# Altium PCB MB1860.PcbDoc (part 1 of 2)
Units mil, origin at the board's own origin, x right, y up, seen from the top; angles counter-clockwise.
Board outline 5005.03 x 3784.67 mil, 2 copper layers (Top Layer, Bottom Layer), stack 61.811 mil thick; 42 components, 46 nets, 183 pads, 524 vias.
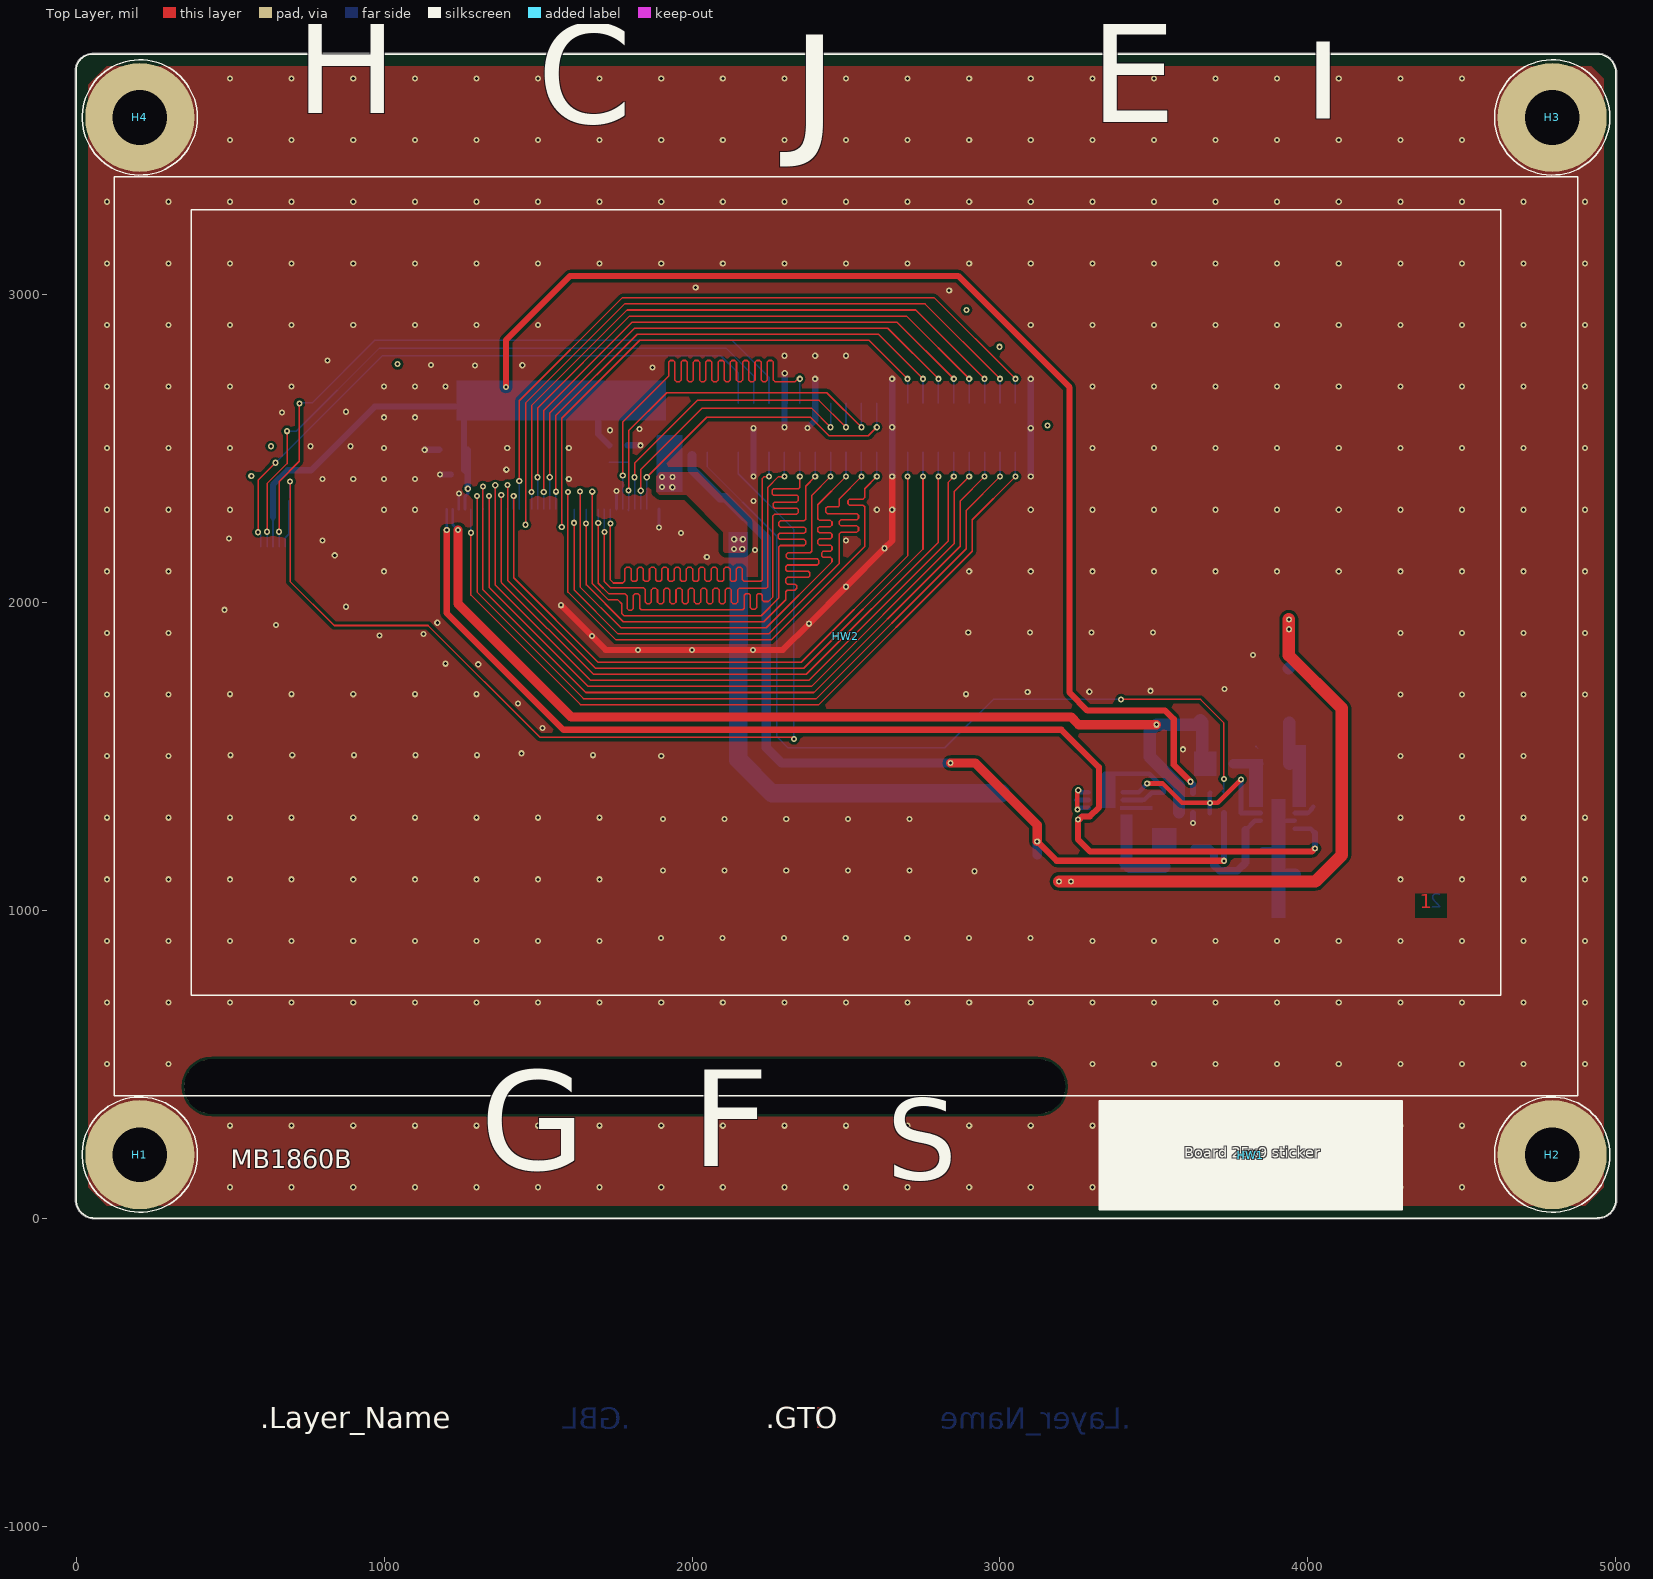
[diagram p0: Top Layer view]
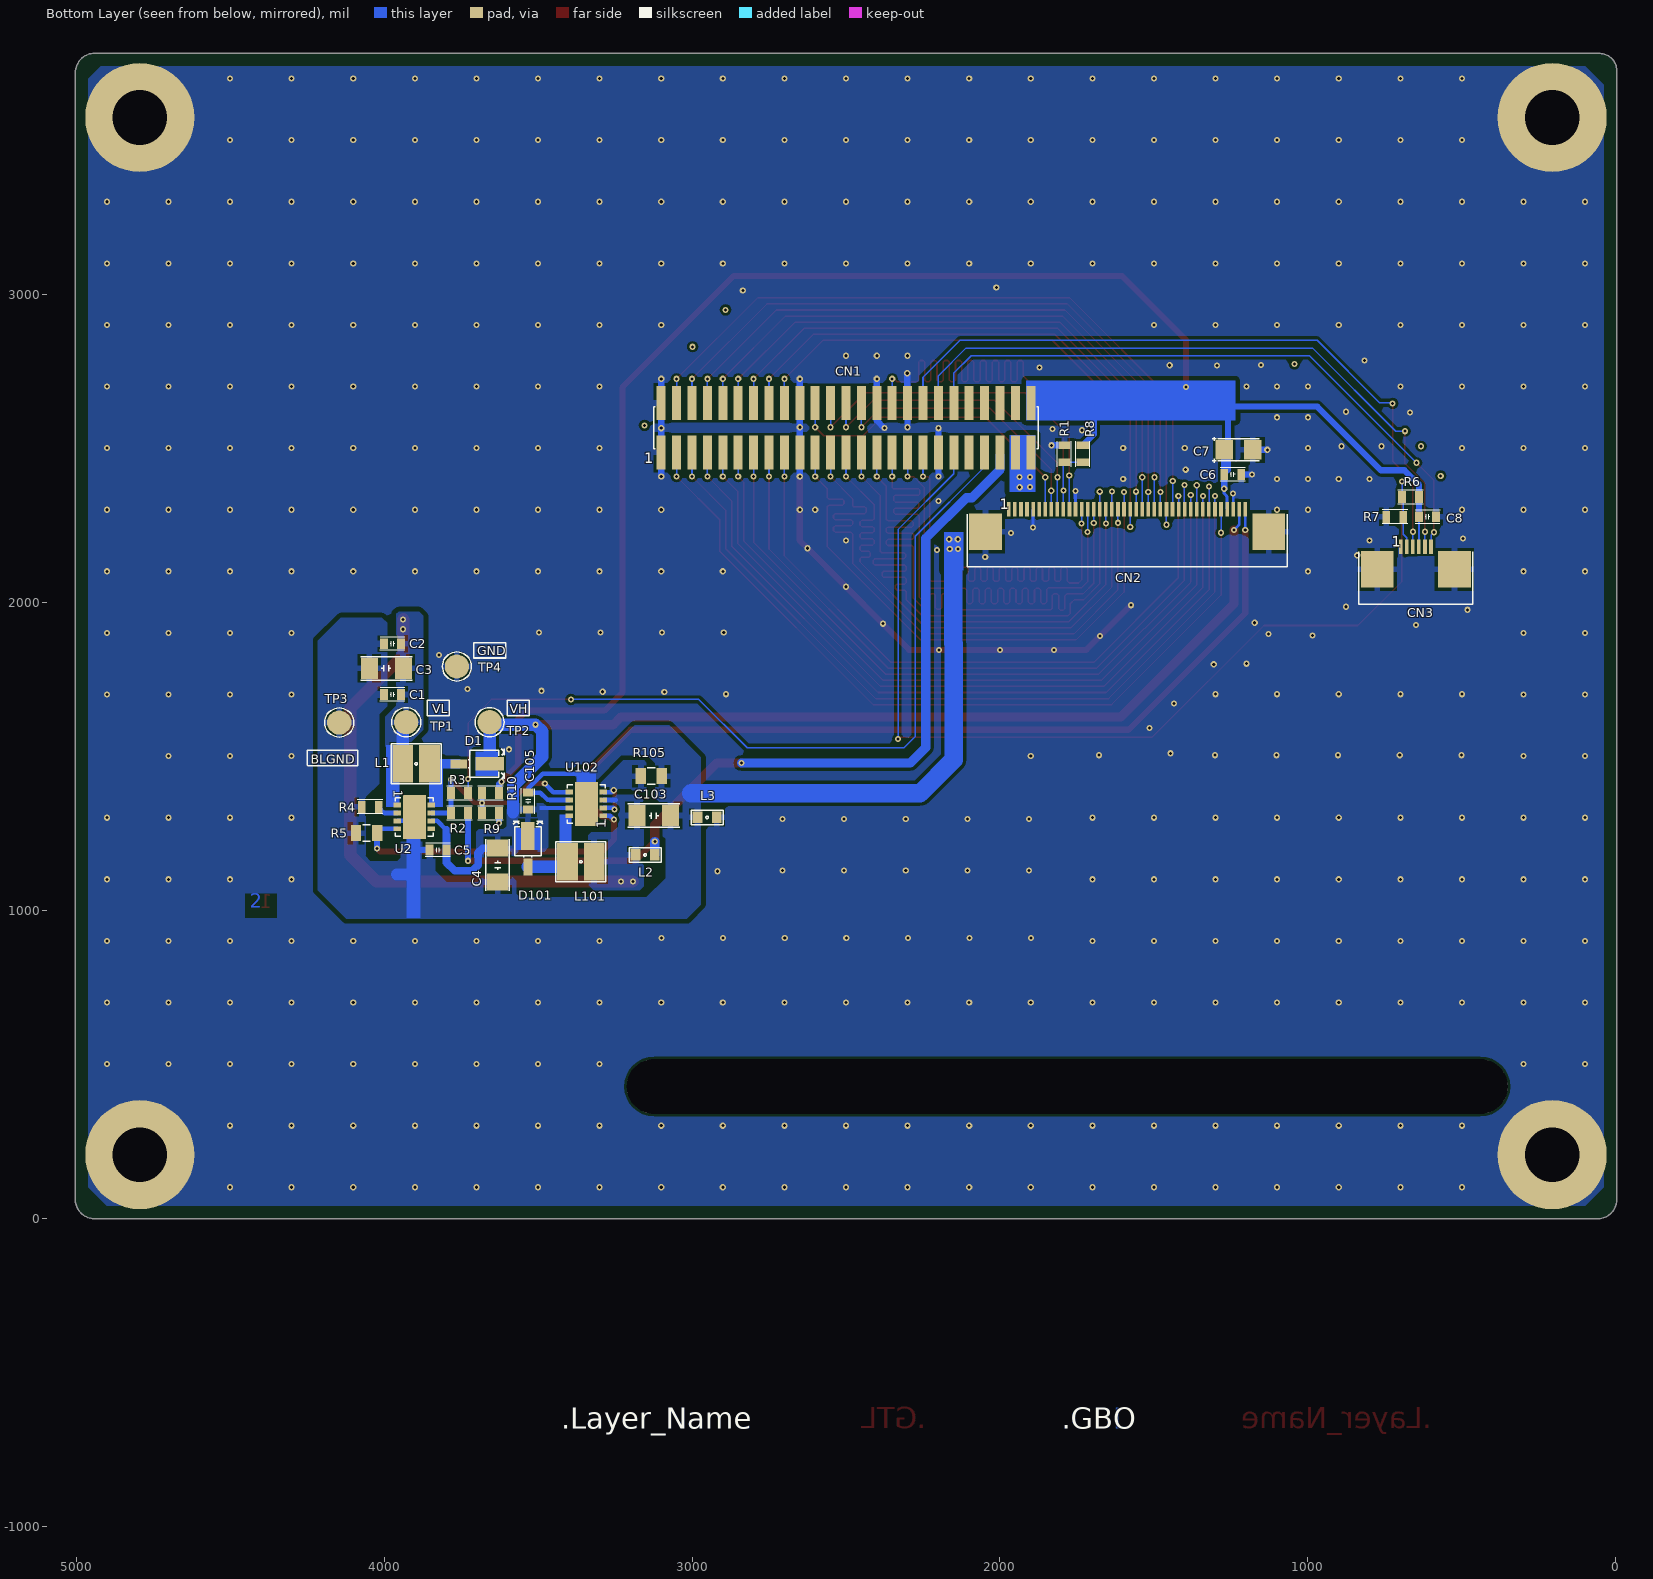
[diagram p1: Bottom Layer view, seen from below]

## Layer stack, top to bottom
Top Solder: solder mask 0.591, Solder Resist, Dk 3.5
Top Layer: signal copper 1.378
Dielectric 1: dielectric 59.055, FR-4, Dk 4.8
Bottom Layer: signal copper 1.378
Bottom Solder: solder mask 0.591, Solder Resist, Dk 3.5

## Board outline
-2.51,57 -2.51,59.51 cw(c60.38,60.26) -2.51,61.01 -2.51,3726 cw(c0,3726) -2.49,3726.34 cw(c0,3726.65) -2.51,3726.68 cw(c53.06,3726) 51.58,3781.56 cw(c53.06,3779.53) 53.06,3782.04 4939.79,3782.04 cw(c4940,3779.54) 4940.03,3782.05 cw(c4939.27,3719.16) 5002.15,3720.31 cw(c5000,3719) 5002.51,3719 5002.51,58 cw(c5000,58) 5002.43,57.34 cw(c4939.62,60.73) 4941.33,-2.14 cw(c4940,0) 4940,-2.52 62.36,-2.52 cw(c61.64,-0.1) 61.69,-2.62 cw(c60.38,60.26) -2.39,56.21 cw(c0,57)

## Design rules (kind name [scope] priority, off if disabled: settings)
Clearance Clearance_1 [HasFootprint('ICC_QFN8-EPAD_3X3_P065')] p1: gap=7.87 ignorepadtopadclearanceinfootprint=FALSE except(0: Arc-Hole Track-Hole SMDPad-Hole THPad-Hole Via-Hole Fill-Hole Poly-Hole Region-Hole Text-Hole; 5: SMDPad-SMDPad; 6: Arc-Via Track-Via Via-Via Via-Fill Via-Poly Via-Region Via-Text; 10: Arc-Arc Arc-Track Arc-Fill Arc-Poly Arc-Region Track-Track Track-Fill Track-Poly Track-Region; 15: Fill-Fill Fill-Poly Fill-Region Poly-Poly Poly-Region Region-Region)
Clearance [All] p2: gap=7.87 ignorepadtopadclearanceinfootprint=FALSE except(0: Arc-Hole Track-Hole SMDPad-Hole THPad-Hole Via-Hole Fill-Hole Poly-Hole Region-Hole Text-Hole; 6: Arc-Via Track-Via; 10: Arc-Arc Arc-Track Arc-Fill Arc-Poly Arc-Region Track-Track Track-Fill Track-Poly Track-Region; 15: Fill-Fill Fill-Poly Fill-Region Poly-Poly Poly-Region Region-Region)
ComponentClearance [All] p1: gap=7.87 collisioncheckmode=3 verticalgap=7.87 showdistances=FALSE
HoleSize [All] p1: absolutevalues=TRUE maxlimit=3937.01 minlimit=1 maxpercent=80.000 minpercent=20.000
MinimumSolderMaskSliver [All] p1: minsoldermaskwidth=0
PlaneConnect [All] p1: planeconnectstyle=Relief reliefexpansion=20 reliefentries=4 reliefconductorwidth=8.27 reliefairgap=8.27
PolygonConnect PolygonConnect_hole [HasFootprint('PTH_450_900')] p1: connectstyle=Direct reliefconductorwidth=10 reliefentries=4 polygonreliefangle="90 Angle" airgapwidth=10
PolygonConnect PolygonConnect_via [IsVia] p2: connectstyle=Direct reliefconductorwidth=10 reliefentries=4 polygonreliefangle="90 Angle" airgapwidth=10
PolygonConnect [All] p3: connectstyle=Relief reliefconductorwidth=20 reliefentries=4 polygonreliefangle="90 Angle" airgapwidth=10
RoutingVias [All] p1: holewidth=11.81 width=31.5 viastyle="Through Hole" minholewidth=11.81 minwidth=31.5 maxholewidth=11.81 maxwidth=31.5
SilkToSilkClearance [All] p1: silktosilkclearance=0
SilkToSolderMaskClearance [IsPad] p1: minsilkscreentomaskgap=0 clearancetoexposedcopper=TRUE
SolderMaskExpansion [All] p1: expansion=4
Width [All] p1: maxlimit=200 minlimit=5 preferedwidth=5
24 further rules are at their usual default settings.

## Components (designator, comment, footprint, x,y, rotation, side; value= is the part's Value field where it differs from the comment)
C1 "Capacitor" C0603 3972.39,1700 r180 bottom value=100nF
C2 "Capacitor" C0603 3972.39,1865 r180 bottom value=10nF
C3 "Capacitor" C1206_H1P25 3992.5,1785 r180 bottom value=4.7uF
C4 "Capacitor" C1206_H1P25 3631,1146 r90 bottom value=4.7uF
C5 "Capacitor" C0603 3824.94,1195 r180 bottom value=10nF
C6 "Capacitor" C0603 1244.44,2414.54 r0 bottom value=100nF
C7 "Cap_POL_TANA" CPOL_TAJ-A_1206_H180 1225.74,2494.54 r180 bottom value=4.7uF
C8 "Capacitor" C0603 612,2276.86 r0 bottom value=100nF
C103 "Capacitor" C1206_H1P25 3124.24,1307 r0 bottom value=4.7uF
C105 "Capacitor" C0603 3532,1353.87 r270 bottom value=100nF
CN1 "Header 25x2 LCD MODULE" CON_SAMTEC_FTSH-125-01-F-DV-K 2500,2566.22 r180 bottom locked value="Header 25x2"
CN2 "68714014022" CON_WE_68714014022 1587.4,2265.08 r180 bottom value=Socket_FFC/FPC_68714014022
CN3 "68710614022" CON_WE_68710614022 649.61,2143.05 r180 bottom value=Socket_FFC/FPC_68710614022
D1 "STPS1L40M" DIO_DO216-AA 3697.74,1475 r0 bottom
D101 "STPS1L40M" DIO_DO216-AA 3533,1199.87 r270 bottom
H1 "POSITION HOLE" PTH_450_900 207.09,205.91 r0 top locked
H2 "POSITION HOLE" PTH_450_900 4792.91,205.91 r0 top locked
H3 "POSITION HOLE" PTH_450_900 4792.91,3573.62 r0 top locked
H4 "POSITION HOLE" PTH_450_900 207.09,3573.62 r0 top locked
HW1 "STICKER_BOARD" STICKER_BOARD_25X9 3814,204 r0 top value="Sticker board"
HW2 "LCD_MODULE" LCD_DRAWING_ROCKTEK_RK050HR18-CTG 2499.99,1889.75 r0 top locked value=RK050HR18-CTG
L1 "Inductor" L1210_LQH 3895.69,1475 r180 bottom value=4.7uH
L2 "BEAD" L0603 3152.24,1179 r0 bottom value="600R @ 100MHz"
L3 "BEAD" L0603 2951,1301 r0 bottom value="600R @ 100MHz"
L101 "Inductor" L1210_LQH 3361,1157 r0 bottom value=4.7uH
R1 "Resistor" R0603 1790.72,2481.54 r270 bottom value=4K7
R2 "Resistor" R0603 3754.83,1315 r0 bottom value=4K7
R3 "Resistor" R0603 3754.83,1380 r0 bottom value=0R
R4 "Resistor" R0603 4044.94,1335 r180 bottom value=100K
R5 "Resistor" R0805_H0P5 4056.83,1250 r180 bottom value=6R2
R6 "Resistor" R0603 667,2340.86 r180 bottom value=220K
R7 "Resistor" R0603 718,2276.86 r180 bottom value=220K
R8 "Resistor" R0603 1731.43,2481.54 r270 bottom value=4K7
R9 "Resistor" R0603 3654,1315 r180 bottom value=4K7
R10 "Resistor" R0603 3654,1380 r0 bottom value=4K7
R105 "Resistor" R0805_H0P5 3132.24,1435 r0 bottom value=6R2
TP1 "Test Point" TP_SMD_2MM 3928,1610 r90 bottom
TP2 "Test Point" TP_SMD_2MM 3657.39,1610 r180 bottom
TP3 "Test Point" TP_SMD_2MM 4145.39,1609 r270 bottom
TP4 "Test Point" TP_SMD_2MM 3763.39,1791 r270 bottom
U2 "STLD40DPUR" ICC_QFN8-EPAD_3X3_P065 3901.6,1302.36 r270 bottom
U102 "TPS61042DRB" ICC_QFN8-EPAD_3X3_P065 3343.24,1344.56 r90 bottom

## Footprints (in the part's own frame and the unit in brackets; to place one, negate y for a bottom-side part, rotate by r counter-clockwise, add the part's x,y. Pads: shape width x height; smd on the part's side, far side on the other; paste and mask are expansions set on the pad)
C0603 [mm]
  rect 0.64x0.89 smd mask+0.05: 1(-0.7,0) 2(0.7,0)
  silkscreen extent -1.05,-0.55 1.02,0.55, body extent -0.9,-0.5 0.9,0.5, height 1.4
C1206_H1P25 [mm]
  rect 1.4x1.78 smd mask+0.05: 1(-1.4,0) 2(1.4,0)
  silkscreen extent -2.12,-0.97 2.15,0.97, body extent -1.7,-0.9 1.7,0.9, height 1.45
CON_SAMTEC_FTSH-125-01-F-DV-K [mm]
  rect 0.74x2.79 smd mask+0.05: 1(-15.24,-2.035) 2(-15.24,2.035) 3(-13.97,-2.035) 4(-13.97,2.035) 5(-12.7,-2.035) 6(-12.7,2.035) 7(-11.43,-2.035) 8(-11.43,2.035) 9(-10.16,-2.035) 10(-10.16,2.035) 11(-8.89,-2.035) 12(-8.89,2.035) 13(-7.62,-2.035) 14(-7.62,2.035) 15(-6.35,-2.035) 16(-6.35,2.035) 17(-5.08,-2.035) 18(-5.08,2.035) 19(-3.81,-2.035) 20(-3.81,2.035) 21(-2.54,-2.035) 22(-2.54,2.035) 23(-1.27,-2.035) 24(-1.27,2.035) 25(0,-2.035) 26(0,2.035) 27(1.27,-2.035) 28(1.27,2.035) 29(2.54,-2.035) 30(2.54,2.035) 31(3.81,-2.035) 32(3.81,2.035) 33(5.08,-2.035) 34(5.08,2.035) 35(6.35,-2.035) 36(6.35,2.035) 37(7.62,-2.035) 38(7.62,2.035) 39(8.89,-2.035) 40(8.89,2.035) 41(10.16,-2.035) 42(10.16,2.035) 43(11.43,-2.035) 44(11.43,2.035) 45(12.7,-2.035) 46(12.7,2.035) 47(13.97,-2.035) 48(13.97,2.035) 49(15.24,-2.035) 50(15.24,2.035)
  silkscreen extent -15.88,-1.71 15.88,1.71, body extent -15.88,-2.92 15.88,2.92, height 6.12
CON_WE_68710614022 [mm] "MCD-02725"
  rect 0.3x1.2 smd mask+0.05: 1(-1.25,0.93) 2(-0.75,0.93) 3(-0.25,0.93) 4(0.25,0.93) 5(0.75,0.93) 6(1.25,0.93)
  rect 2.7x3 smd mask+0.05: MP1(-3.18,-0.93) MP2(3.18,-0.93)
  silkscreen extent -4.7,-3.8 4.7,0.52, body extent -4.7,-3.73 4.7,1.37, height 2.1
CON_WE_68714014022 [mm] "MCD-027xx"
  rect 0.3x1.2 smd mask+0.05: 1(-9.75,0.93) 2(-9.25,0.93) 3(-8.75,0.93) 4(-8.25,0.93) 5(-7.75,0.93) 6(-7.25,0.93) 7(-6.75,0.93) 8(-6.25,0.93) 9(-5.75,0.93) 10(-5.25,0.93) 11(-4.75,0.93) 12(-4.25,0.93) 13(-3.75,0.93) 14(-3.25,0.93) 15(-2.75,0.93) 16(-2.25,0.93) 17(-1.75,0.93) 18(-1.25,0.93) 19(-0.75,0.93) 20(-0.25,0.93) 21(0.25,0.93) 22(0.75,0.93) 23(1.25,0.93) 24(1.75,0.93) 25(2.25,0.93) 26(2.75,0.93) 27(3.25,0.93) 28(3.75,0.93) 29(4.25,0.93) 30(4.75,0.93) 31(5.25,0.93) 32(5.75,0.93) 33(6.25,0.93) 34(6.75,0.93) 35(7.25,0.93) 36(7.75,0.93) 37(8.25,0.93) 38(8.75,0.93) 39(9.25,0.93) 40(9.75,0.93)
  rect 2.7x3 smd mask+0.05: MP1(-11.68,-0.93) MP2(11.68,-0.93)
  silkscreen extent -13.2,-3.8 13.2,0.52, body extent -13.2,-3.7 13.2,1.4, height 2.15
CPOL_TAJ-A_1206_H180 [mm]
  rect 1.45x1.6 smd mask+0.05: 1(-1.175,0) 2(1.175,0)
  silkscreen extent -2.15,-1.05 1.7,1.05, body extent -1.7,-0.9 1.7,0.9, height 1.8
DIO_DO216-AA [mm]
  rect 1.38x0.75 smd mask+0.05: 1(1.515,0)
  rect 2.32x1.1 smd mask+0.05: 2(-1.045,0)
  Top Layer region: -1.705,1.015 0.115,1.015 0.115,-1.015 -1.705,-1.015
  silkscreen extent -2.25,-1.22 0.72,1.22, body extent -2.02,-1.02 1.83,1.02, height 1.15
ICC_QFN8-EPAD_3X3_P065 [mm]
  rect 0.4x0.6 smd paste+0 mask+0.05: 1(-0.975,-1.4) 2(-0.325,-1.4) 3(0.325,-1.4) 4(0.975,-1.4) 5(0.975,1.4) 6(0.325,1.4) 7(-0.325,1.4) 8(-0.975,1.4)
  rect 3.6x1.9 smd paste+0 mask+0: 9(0,0)
  silkscreen extent -1.58,-1.58 1.58,1.58, body extent -1.58,-1.58 1.58,1.58, height 1
L0603 [mm]
  rect 0.8x0.95 smd mask+0.05: 1(-0.8,0) 2(0.8,0)
  silkscreen extent -1.33,-0.6 1.33,0.6, body extent -0.87,-0.47 0.87,0.47, height 0.95
L1210_LQH [mm]
  rect 1.7x3.1 smd mask+0.05: 1(-1.1,0) 2(1.1,0)
  silkscreen extent -2.05,-1.65 2.05,1.65, body extent -1.75,-1.35 1.75,1.35, height 2
LCD_DRAWING_ROCKTEK_RK050HR18-CTG [mil] "MCD-02602"
  silkscreen extent -2376,-1492 2376,1492, body extent -2376,-1492 2376,1492, height 191
PTH_450_900 [mm] "MCD-01612"
  round 9 hole 4.5 mask+0.05: 1(0,0)
  silkscreen extent -4.75,-4.75 4.75,4.75
R0603 [mm]
  rect 0.64x1 smd mask+0.05: 1(-0.7,0) 2(0.7,0)
  silkscreen extent -1.05,-0.58 1.05,0.58, body extent -0.9,-0.5 0.9,0.5, height 0.56
R0805_H0P5 [mm] "MCD-01537"
  rect 0.85x1.3 smd mask+0.05: 1(-0.875,0) 2(0.875,0)
  silkscreen extent -0.33,-0.67 0.33,0.67, body extent -1.05,-0.68 1.05,0.68, height 0.6
STICKER_BOARD_25X9 [mil] "Sticker to mention board CPN code"
  silkscreen extent -492,-177 492,177
TP_SMD_2MM [mm]
  round 2 smd paste-10 mask+0.05: 1(0,0)
  silkscreen extent -1.2,-1.2 1.2,1.2

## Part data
C1 C6 C8: library part MCD-00211, "Capacitor, MLCC, 100nF, 16V, X7R, +/-10%, 0603, T=0.8mm", Manufacturer=YAGEO, Manufacturer_Part_Number=CC0603KRX7R7BB104, Package=0603
C2 C5: library part MCD-00017, "Capacitor, MLCC, 10nF, 50V, X7R, +/-10%, 0603, T=0.8mm", Manufacturer=YAGEO, Manufacturer_Part_Number=CC0603KRX7R9BB103, Package=0603
C3 C4 C103: library part MCD-00013, "Capacitor, MLCC, 4.7uF, 50V, X7R, +/-10%, 1206, T=1.27mm", Manufacturer=AVX, Manufacturer_Part_Number=12065C475KAT2A, Package=1206
C7: library part MCD-00007, "Capacitor, Tantalum, 4.7uF, 16V, 4R, +/-10%, Type_A (3216 metric), T=1.6mm", Manufacturer=AVX, Manufacturer_Part_Number=TAJA475K016R, Package="3216 (metric)"
C105: library part MCD-01099, "Capacitor, MLCC, 100nF, 50V, X7R, +/-10%, 0603, T=0.8mm", Manufacturer=YAGEO, Manufacturer_Part_Number=CC0603KRX7R9BB104, Package=0603
CN1: library part MCD-01187, "Header, 25x2, 1.27mm, VR, SMD, T=3.05mm", Manufacturer=SAMTEC, Manufacturer_Part_Number=FTSH-125-01-F-DV-K
CN2: library part MCD-02724, "Socket_FFC/FPC, 40pins, 0.5mm, RA, SMD, T=2.1mm, TOP Contact", Manufacturer="WURTH ELEKTRONIK"
CN3: library part MCD-02725, "Socket_FFC/FPC, 6pins, 0.5mm, RA, SMD, T=2.1mm, TOP Contact", Manufacturer="WURTH ELEKTRONIK"
D1 D101: library part MCD-00033, "Low Drop power Schottky rectifier(1A, 40V, 0.4V)", Manufacturer=STMICROELECTRONICS, Manufacturer_HQ_COO=EU
H1 H2 H3 H4: library part MCD-01612, "POSITION HOLE C9D4R5", Manufacturer=N/A
HW1: library part MCD-00235, "Sticker Board 25x9 mm", Manufacturer=N/A
HW2: library part MCD-02602, "LCD, 5.0 inch, TFT, 800*480 Pixels with LED backlight, All viewing angle, Capacitive Panel", Manufacturer=ROCKTECH, Manufacturer_Part_Number=RK050HR18-CTG
L1 L101: library part MCD-00048, "Inductor, 4.7uH, +/-30%, 1A, 180mR, 1210, T=1.7mm", Manufacturer=MURATA, Manufacturer_Part_Number=LQH32PN4R7NN0L, Package=1210
L2 L3: library part MCD-00047, "Ferrite bead, 600R @1 00MHz, +/-25%, 350mA, 0R5, 0603, T=0.8mm", Manufacturer=TAI-TECH, Manufacturer_Part_Number=FCM1608KF-601T03, Package=0603
R1 R2 R8 R9 R10: library part MCD-00219, "Resistor, 4K7, 0603, +/-1%, 1/10W", Manufacturer=YAGEO, Manufacturer_Part_Number=RC0603FR-074K7L, Package=0603
R3: library part MCD-00056, "Resistor, 0R, 0603, +/-5%, 1/10W", Manufacturer=YAGEO, Manufacturer_Part_Number=RC0603JR-070RL, Package=0603
R4: library part MCD-00223, "Resistor, 100K, 0603, +/- 1%, 1/10W", Manufacturer=YAGEO, Manufacturer_Part_Number=RC0603FR-07100KL, Package=0603
R5 R105: library part MCD-02728, "Resistor, 6R2, 0805, +/-1%, 1/8W", Manufacturer=YAGEO, Manufacturer_Part_Number=RC0805FR-076R2L
R6 R7: library part MCD-00347, "Resistor, 220K, 0603, +/-1%, 1/10W", Manufacturer=YAGEO, Manufacturer_Part_Number=RC0603FR-07220KL, Package=0603
TP1 TP2 TP3 TP4: library part MCD-00177, "Test Point 2mm", Manufacturer=N/A
U2: library part MCD-00082, "White LED power supply for large display backlight, QFN8", Manufacturer=STMICROELECTRONICS, Manufacturer_HQ_COO=EU
U102: library part MCD-02727, "30-V, 500-mA switch boost converter in QFN-8 for white LED applications", Manufacturer="TEXAS INSTRUMENTS"

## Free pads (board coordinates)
  round 20 on Mech16: 1(1057.63,-954.91) 1(2980.76,-954.91)
  oval 2860x177.17 hole 177.17 slot 2860 at 0 deg unplated: ""(1781.62,427.1)

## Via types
v1: diameter 20, hole 10, Top Layer to Bottom Layer, tented both sides, 524 vias

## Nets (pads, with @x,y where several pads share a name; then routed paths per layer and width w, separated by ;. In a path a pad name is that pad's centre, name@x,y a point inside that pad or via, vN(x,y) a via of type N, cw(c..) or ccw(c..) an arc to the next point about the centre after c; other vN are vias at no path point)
B0: CN1.21 CN2.20 | length 1952
  Top Layer w5: v1(1597.24,2357.54) 1597.24,2032.89 1752.92,1877.21 2257.08,1877.21 2560.55,2180.7 2560.55,2309.5 2555.55,2314.5 2511.55,2314.5 2506.55,2319.5 2506.55,2329.5 2511.55,2334.5 2555.55,2334.5 2560.55,2339.5 2560.55,2367.99 v1@2600,2407.44
  Bottom Layer w5: CN2.20@1597.25,2301.69 v1(1597.24,2357.54) ; v1(2600,2407.44) CN1.21@2600,2486.1
B1: CN1.23 CN2.19 | length 1974.1
  Top Layer w5: v1(1616.93,2257.54) 1616.93,2040.07 1760.11,1896.89 2248.92,1896.89 2478.55,2126.52 2478.55,2222.28 2483.55,2227.28 2535.55,2227.28 2540.55,2232.28 2540.55,2242.28 2535.55,2247.28 2483.55,2247.28 2478.55,2252.28 2478.55,2262.28 2483.55,2267.28 2535.55,2267.28 2540.55,2272.28 2540.55,2282.28 2535.55,2287.28 2439.55,2287.28 2434.55,2292.28 2434.55,2304.46 2439.55,2309.46 2474.55,2309.46 2478.55,2313.46 2478.55,2335.99 v1(2550,2407.44)
  Bottom Layer w5: v1(1616.93,2257.54) CN2.19@1616.93,2301.69 ; v1(2550,2407.44) CN1.23@2550,2486.1
B2: CN1.25 CN2.18 | length 1979.4
  Top Layer w5: 1636.61,2049.96 1637,2049.57 1636.61,2049.19 ; v1(1636.61,2359.54) 1636.61,2049.19 ; v1@2500,2407.44 2408.55,2315.99 2408.55,2270.36 2413.55,2265.36 2449.55,2265.36 2454.55,2260.36 2454.55,2250.36 2449.55,2245.36 2413.55,2245.36 2408.55,2240.36 2408.55,2230.36 2413.55,2225.36 2449.55,2225.36 2454.55,2220.36 2454.55,2210.36 2449.55,2205.36 2413.55,2205.36 2408.55,2200.36 2408.55,2190.36 2413.55,2185.36 2449.55,2185.36 2454.55,2180.36 2454.55,2170.36 2449.55,2165.36 2426.36,2165.36 2422,2161 2422,2149.36 2426,2145.36 2449.55,2145.36 2454.55,2140.36 2454.55,2130.36 2240.77,1916.58 1769.23,1916.58 1636.61,2049.19
  Bottom Layer w5: CN2.18@1636.62,2301.69 v1(1636.61,2359.54) ; v1(2500,2407.44) CN1.25@2500,2486.1
B3: CN1.27 CN2.17 | length 1956.9
  Top Layer w5: v1(1656.3,2255.54) 1656.3,2056.7 1657,2056 1776.73,1936.26 2232.61,1936.26 2304.18,2007.83 2304.18,2033.65 2309.18,2038.65 2333.65,2038.65 2340,2045 2340,2053 2334.35,2058.65 2309.18,2058.65 2304.18,2063.65 2304.18,2075.09 2309.18,2080.09 2377.55,2080.09 2382.55,2085.09 2382.55,2095.09 2377.55,2100.09 2309.18,2100.09 2304.18,2105.09 2304.18,2115.09 2309.55,2120.46 2406.46,2120.46 2412,2126 2412,2135 2406.54,2140.46 2311.55,2140.46 2306.55,2145.46 2306.55,2155.46 2311.55,2160.46 2383.74,2160.46 2388.74,2165.46 2388.74,2346.18 v1(2450,2407.44)
  Bottom Layer w5: v1(1656.3,2255.54) CN2.17@1656.3,2301.69 ; v1(2450,2407.44) CN1.27@2450,2486.1
B4: CN1.29 CN2.16 | length 1944
  Top Layer w5: v1(1676,2358.54) 1675.98,2060.02 1729,2007 1759.3,2007 1772,1994.3 1772,1963 1779.05,1955.95 2224.46,1955.95 2281.55,2013.04 2281.55,2178.77 2286.55,2183.77 2364.05,2183.77 2369.05,2188.77 2369.05,2198.77 2364.05,2203.77 2284.55,2203.77 2279.55,2208.77 2279.55,2218.46 2284.86,2223.77 2364.05,2223.77 2369.05,2228.77 2369.05,2238.77 2364.05,2243.77 2286.55,2243.77 2281.55,2248.77 2281.55,2258.77 2286.55,2263.77 2364.05,2263.77 2369.05,2268.77 2369.05,2376.5 v1(2400,2407.44)
  Bottom Layer w5: CN2.16@1676,2301.71 v1(1676,2358.54) ; v1(2400,2407.44) CN1.29@2400,2486.1
B5: CN1.31 CN2.15 | length 1982.9
  Top Layer w5: v1(1695.67,2256.54) 1695.67,2061.55 1730.76,2026.46 1783.54,2026.46 1789.06,2020.94 1789.06,1979.14 1794.06,1974.14 1804.06,1974.14 1809.06,1979.14 1809.06,2021.46 1814.06,2026.46 1825.12,2026.46 1830.12,2021.46 1830.12,1980.4 1835.12,1975.4 2164.69,1975.4 2169.69,1980.4 2169.69,2022.46 2174.69,2027.46 2184.69,2027.46 2189.69,2022.46 2189.69,1981.46 2194.69,1976.46 2204.69,1976.46 2209.69,1981.46 2209.69,2022.46 2214.69,2027.46 2223,2027.46 2228,2022.46 2228,2007 2233,2002 2248,2002 2262.55,2016.55 2262.55,2279.99 2267.55,2284.99 2339.55,2284.99 2345.55,2290.99 2345.55,2299.99 2340.55,2304.99 2268.55,2304.99 2263.55,2309.99 2263.55,2319.99 2268.55,2324.99 2339.55,2324.99 2345.55,2330.99 2345.55,2342.4 2340.55,2347.4 2264.6,2347.4 2261,2351 2261,2364 2264.4,2367.4 2345,2367.4 2350,2372.4 v1(2350,2407.44)
  Bottom Layer w5: v1(1695.67,2256.54) CN2.15@1695.67,2301.69 ; v1(2350,2407.44) CN1.31@2350,2486.1
B6: CN1.33 CN2.14 | length 1941.7
  Top Layer w5: v1(1715.35,2228.19) 1715.35,2066.65 1736,2046 1843,2046 1847.99,2041.01 1847.99,2000.32 1852.99,1995.32 1862.99,1995.32 1867.99,2000.32 1867.99,2039.46 1872.99,2044.46 1882.99,2044.46 1887.99,2039.46 1887.99,2000.32 1892.99,1995.32 1902.99,1995.32 1907.99,2000.32 1907.99,2039.46 1912.99,2044.46 1922.99,2044.46 1927.99,2039.46 1927.99,2000.32 1932.99,1995.32 1942.99,1995.32 1947.99,2000.32 1947.99,2039.46 1952.99,2044.46 1962.99,2044.46 1967.99,2039.46 1967.99,2000.32 1972.99,1995.32 1982.99,1995.32 1987.99,2000.32 1987.99,2039.46 1992.99,2044.46 2002.99,2044.46 2007.99,2039.46 2007.99,2000.32 2012.99,1995.32 2022.99,1995.32 2027.99,2000.32 2027.99,2039.46 2032.99,2044.46 2042.99,2044.46 2047.99,2039.46 2047.99,2000.32 2052.99,1995.32 2062.99,1995.32 2067.99,2000.32 2067.99,2039.46 2072.99,2044.46 2082.99,2044.46 2087.99,2039.46 2087.99,2000.32 2092.99,1995.32 2102.99,1995.32 2107.99,2000.32 2107.99,2039.46 2112.99,2044.46 2122.99,2044.46 2127.99,2039.46 2127.99,2000.32 2132.99,1995.32 2142.99,1995.32 2147.99,2000.32 2147.99,2039.46 2152.99,2044.46 2240.55,2044.46 2245.55,2049.46 2245.55,2372.55 2280.44,2407.44 v1(2300,2407.44)
  Bottom Layer w5: v1(1715.35,2228.19) 1715.35,2298.99 1714,2300.34 CN2.14@1715.36,2301.69 ; v1(2300,2407.44) CN1.33@2300,2486.1
B7: CN1.35 CN2.13 | length 1948.2
  Top Layer w5: v1(1735.04,2255.54) 1735.04,2071.96 1745,2062 1775,2062 1781.98,2068.98 1781.98,2107.46 1786.98,2112.46 1796.98,2112.46 1801.98,2107.46 1801.98,2072.46 1806.98,2067.46 1816.98,2067.46 1821.98,2072.46 1821.98,2107.46 1826.98,2112.46 1836.98,2112.46 1841.98,2107.46 1841.98,2072.46 1846.98,2067.46 1856.98,2067.46 1861.98,2072.46 1861.98,2107.46 1866.98,2112.46 1876.98,2112.46 1881.98,2107.46 1881.98,2072.46 1886.98,2067.46 1896.98,2067.46 1901.98,2072.46 1901.98,2107.46 1906.98,2112.46 1916.98,2112.46 1921.98,2107.46 1921.98,2072.46 1926.98,2067.46 1936.98,2067.46 1941.98,2072.46 1941.98,2107.46 1946.98,2112.46 1956.98,2112.46 1961.98,2107.46 1961.98,2072.46 1966.98,2067.46 1976.98,2067.46 1981.98,2072.46 1981.98,2107.46 1986.98,2112.46 1996.98,2112.46 2001.98,2107.46 2001.98,2072.46 2006.98,2067.46 2016.98,2067.46 2021.98,2072.46 2021.98,2107.46 2026.98,2112.46 2036.98,2112.46 2041.98,2107.46 2041.98,2072.46 2046.98,2067.46 2056.98,2067.46 2061.98,2072.46 2061.98,2107.46 2066.98,2112.46 2076.98,2112.46 2081.98,2107.46 2081.98,2072.46 2086.98,2067.46 2098.55,2067.46 2103.55,2072.46 2103.55,2107.46 2108.55,2112.46 2118.55,2112.46 2123.55,2107.46 2123.55,2072.46 2128.55,2067.46 2138.55,2067.46 2143.55,2072.46 2143.55,2107.46 2148.55,2112.46 2158.55,2112.46 2163.55,2107.46 2163.55,2072.46 2168.55,2067.46 2223.55,2067.46 2228.55,2072.46 2228.55,2401.55 2234.44,2407.44 v1(2250,2407.44)
  Bottom Layer w5: v1(1735.04,2255.54) CN2.13@1735.04,2301.69 ; v1(2250,2407.44) CN1.35@2250,2486.1
BL_A: C4.2 C5.2 C105.2 CN2.39 D1.2 D101.2 TP2.1 U2.6 U102.7 | length 3766.3
  Top Layer w30: v1(1240,2234.54) 1240,1995 1608,1627 3231,1627 3256,1602 v1(3508,1602)
  Bottom Layer w5: TP2.1@3656.6,1609.21 TP2.1@3657.39,1610
  Bottom Layer w9: CN2.39@1223.23,2301.69 1223.23,2252.31 1223.54,2252 1223.54,2251 v1(1240,2234.54)
  Bottom Layer w15: 3797.39,1260 3826.95,1289.57 U2.6@3846.48,1289.57
  Bottom Layer w25: C4.2@3631,1201.12 3678.88,1201.12 3694.77,1185.23 3694.77,1173.73 3694.5,1173.46 3694.5,1146.54 3713.54,1127.5 3770.5,1127.5 3797.39,1154.39 C5.2@3797.39,1195 3797.39,1260
  Bottom Layer w39.37: TP2.1@3651.39,1616 TP2.1@3657.39,1610
  Bottom Layer w40: 3581,1318 3581,1403.3 3486,1498.3 3486,1580 v1(3508,1602) 3635.81,1602 TP2.1@3649.81,1616 ; D1.2@3656.6,1475 TP2.1@3656.6,1609.21
BL_CTRL: CN1.43 R3.1 | length 2820.6
  Top Layer w5: v1@3388,1684 v1(3393,1684) 3651,1684 3727.27,1607.73 v1(3727.27,1425.79)
  Bottom Layer w5: CN1.43@2050,2486.1 2050,2439 2275,2214 2275,1564 2312,1527 2821,1527 2978,1684 v1(3393,1684) ; R3.1@3721.36,1385.91 R3.1@3727.27,1380 v1(3727.27,1425.79)
BL_EN: R2.2 R3.2 R9.1 R10.2 U2.7 U102.5 | length 692.8
  Top Layer w15: v1(3478,1411) 3528,1411 3591,1348 v1(3681.56,1348) 3706.77,1348 v1(3782.39,1423.61)
  Bottom Layer w15: U102.5@3398.35,1382.94 3449.94,1382.94 v1(3478,1411) ; R9.1@3681.56,1315 v1(3681.56,1348) R10.2@3681.56,1380 R10.2@3682.56,1381 ; v1@3782,1424 v1(3782.39,1423.61) R3.2@3782.39,1380 R2.2@3782.39,1315 3782.54,1315.16 U2.7@3846.48,1315.16
BL_K: CN2.40 R5.2 U2.4 U102.1 | length 3892.3
  Top Layer w20: v1(1203.54,2234.54) 1203.54,1964.46 1582.5,1585.5 3199.5,1585.5 3321,1464 3321,1333 3292,1304 3267.13,1304 3257.13,1294 v1(3253.24,1294) 3253.24,1229.76 3293,1190 4012.39,1190 v1(4022.39,1200)
  Bottom Layer w9: v1(1203.54,2234.54) CN2.40@1203.54,2301.69
  Bottom Layer w15: v1(3253.24,1294) 3261.24,1302 3261.59,1302 3265.76,1306.17 U102.1@3288.12,1306.17 ; U2.4@3956.72,1263.98 4008.41,1263.98 R5.2@4022.39,1250
  Bottom Layer w20: v1(4022.39,1200) R5.2@4022.39,1250
BLGND: C1.1 C2.1 C3.1 C4.1 C5.1 C103.1 C105.1 CN1.47 CN1.49 L3.2 R4.1 R5.1 R105.1 TP3.1 U2.3 U2.9 U102.6 U102.9 | length 2048
  Bottom Layer w15: 3340,1443 3484,1443 3532,1395 C105.1@3532,1381.43 3492.79,1381.43 3469.3,1357.94 3462.94,1357.94 3462.35,1357.35 U102.6@3398.35,1357.35 ; U2.9@3901.6,1302.36 3914.39,1289.57 U2.3@3956.72,1289.57
  Bottom Layer w20: C5.1@3852.5,1195 3887.39,1195
  Bottom Layer w39.37: 3907.62,1115 3957.39,1115
  Bottom Layer w60: 2151,2124 2151,1865.7 2150.13,1864.83 2150.13,1488.87 2260,1379 3003,1379
  other v1: 2136,2173 2163,2173 2137,2204 2165,2204 1936,2373 1902,2374 1902,2406 1937,2406
BLVDD: CN1.45 L2.1 R2.1 | length 2934.3
  Top Layer w20: v1(3120.74,1223) 3183.74,1160 v1(3727,1160)
  Top Layer w30: v1(2839.5,1477.5) 2919.5,1477.5 3120.74,1276.26 v1(3120.74,1223)
  Bottom Layer w5: CN1.45@2000,2486.1 CN1.45@2005,2481.1
  Bottom Layer w20: v1(3727,1160) 3727.27,1160.27 R2.1@3727.27,1315
  Bottom Layer w30: CN1.45@2000,2476.1 2000,2430 2091,2339 2109,2339 2241,2207 2241,1528 2291.5,1477.5 v1(2839.5,1477.5) ; L2.1@3120.74,1179 v1(3120.74,1223)
CLK: CN1.32 CN2.11 | length 2117.3
  Top Layer w5: v1(1775,2411.54) 1775,2584.53 1924.47,2734 1924.47,2779.49 1929.47,2784.49 1939.47,2784.49 1944.47,2779.49 1944.47,2721.03 1949.47,2716.03 1959.47,2716.03 1964.47,2721.03 1964.47,2779.49 1969.47,2784.49 1979.47,2784.49 1984.47,2779.49 1984.47,2721.03 1989.47,2716.03 1999.47,2716.03 2004.47,2721.03 2004.47,2779.49 2009.47,2784.49 2019.47,2784.49 2024.47,2779.49 2024.47,2721.03 2029.47,2716.03 2039.47,2716.03 2044.47,2721.03 2044.47,2779.49 2049.47,2784.49 2059.47,2784.49 2064.47,2779.49 2064.47,2721.03 2069.47,2716.03 2079.47,2716.03 2084.47,2721.03 2084.47,2779.49 2089.47,2784.49 2099.47,2784.49 2104.47,2779.49 2104.47,2721.03 2109.47,2716.03 2119.47,2716.03 2124.47,2721.03 2124.47,2779.49 2129.47,2784.49 2139.47,2784.49 2144.47,2779.49 2144.47,2721.03 2149.47,2716.03 2159.47,2716.03 2164.47,2721.03 2164.47,2779.49 2169.47,2784.49 2179.47,2784.49 2184.47,2779.49 2184.47,2721.03 2189.47,2716.03 2199.47,2716.03 2204.47,2721.03 2204.47,2779.49 2209.47,2784.49 2219.47,2784.49 2224.47,2779.49 2224.47,2721.03 2229.47,2716.03 2239.47,2716.03 2244.47,2721.03 2244.47,2779.49 2249.47,2784.49 2259.47,2784.49 2264.47,2779.49 2264.47,2721.03 2269.47,2716.03 2335.59,2716.03 v1@2350.59,2731.03
  Bottom Layer w5: CN2.11@1774.41,2301.69 1774.41,2410.95 v1(1775,2411.54) ; CN1.32@2350,2646.34 v1(2350,2725)
DE: CN1.22 CN2.7 | length 1046.2
  Top Layer w5: v1(1853.15,2405.51) 2047.64,2600 2385,2600 2445,2540 2572.32,2540 v1(2600,2567.68)
  Bottom Layer w5: CN2.7@1853.15,2301.69 1853.15,2387.54 v1(1853.15,2405.51) ; v1(2600,2567.68) CN1.22@2600,2646.34
DISP: CN1.24 CN2.10 R1.2 R8.2 | length 1341.5
  Top Layer w5: v1(1794.09,2362.54) 1794.09,2432.28 ; v1(2550,2567.68) 2437.68,2680 1918,2680 1794.09,2556.09 1794.09,2434.09 ; 1794.09,2432.28 1794.09,2434.09 ; 1794.09,2432.28 1795,2433.19 1794.09,2434.09
  Bottom Layer w5: R8.2@1731.43,2453.98 R1.2@1790.72,2453.98 ; CN2.10@1790.72,2300.44 CN2.10@1794.09,2297.07 ; CN2.10@1794.1,2301.69 v1(1794.09,2362.54) R1.2@1794.09,2450.61 ; v1(2550,2567.68) CN1.24@2550,2646.34
G0: CN1.4 CN2.28 | length 2289.3
  Top Layer w5: v1(1439,2393.54) 1439,2653.87 1772.92,2987.8 2787.2,2987.8 v1(3050,2725)
  Bottom Layer w5: v1(1439,2393.54) 1439.76,2392.78 CN2.28@1439.77,2301.69 ; CN1.4@3050,2646.34 v1(3050,2725)
G1: CN1.6 CN2.27 | length 2299.6
  Top Layer w5: v1(1459.45,2251.09) 1459.45,2645.38 1460,2645.93 1459.45,2646.48 1781.08,2968.11 2756.89,2968.11 v1(3000,2725)
  Bottom Layer w5: v1(1459.45,2251.09) CN2.27@1459.45,2301.69 ; CN1.6@3000,2646.34 v1(3000,2725)
G2: CN1.8 CN2.26 | length 2107.9
  Top Layer w5: v1(1479.13,2357.68) 1479.13,2636.6 1480,2637.46 1479.13,2638.33 1789.23,2948.43 2726.57,2948.43 v1(2950,2725)
  Bottom Layer w5: CN2.26@1479.14,2301.69 v1(1479.13,2357.68) ; CN1.8@2950,2646.34 v1(2950,2725)
G3: CN1.10 CN2.25 | length 2016.4
  Top Layer w5: v1(1498.82,2405.51) 1498.82,2630.17 1797.38,2928.74 2696.26,2928.74 v1(2900,2725)
  Bottom Layer w5: CN2.25@1498.82,2301.69 1498.82,2350.67 v1(1498.82,2405.51) ; CN1.10@2900,2646.34 v1(2900,2725)
G4: CN1.12 CN2.24 | length 1926.7
  Top Layer w5: v1(1518.5,2357.04) 1518,2357.54 1518,2621.52 ; 1518.5,2621.01 1518,2621.52 ; v1(2850,2725) 2665.94,2909.06 1805.54,2909.06 1518,2621.52
  Bottom Layer w5: CN2.24@1518.51,2301.69 v1(1518.5,2357.04) ; CN1.12@2850,2646.34 v1(2850,2725)
G5: CN1.14 CN2.23 | length 1835.3
  Top Layer w5: v1(1537.95,2405.51) 1537.95,2613.97 1813.59,2889.61 2635.39,2889.61 v1(2800,2725)
  Bottom Layer w5: 1537.95,2365.78 v1(1537.95,2405.51) ; CN2.23@1538.19,2301.69 1538.19,2365.78 ; CN1.14@2800,2646.34 v1(2800,2725)
G6: CN1.16 CN2.22 | length 1746
  Top Layer w5: v1(1557.87,2358.54) 1557,2359.42 1557,2604.84 ; 1557.87,2603.96 1557,2604.84 ; v1(2750,2725) 2605.31,2869.69 1821.85,2869.69 1557,2604.84
  Bottom Layer w5: CN2.22@1557.88,2301.69 v1(1557.87,2358.54) ; CN1.16@2750,2646.34 v1(2750,2725)
G7: CN1.18 CN2.21 | length 1770.1
  Top Layer w5: v1(1577,2243.54) 1577,2597 1830,2850 2575,2850 v1(2700,2725)
  Bottom Layer w5: v1(1577,2243.54) 1577,2301.13 CN2.21@1577.56,2301.69 ; CN1.18@2700,2646.34 v1(2700,2725)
